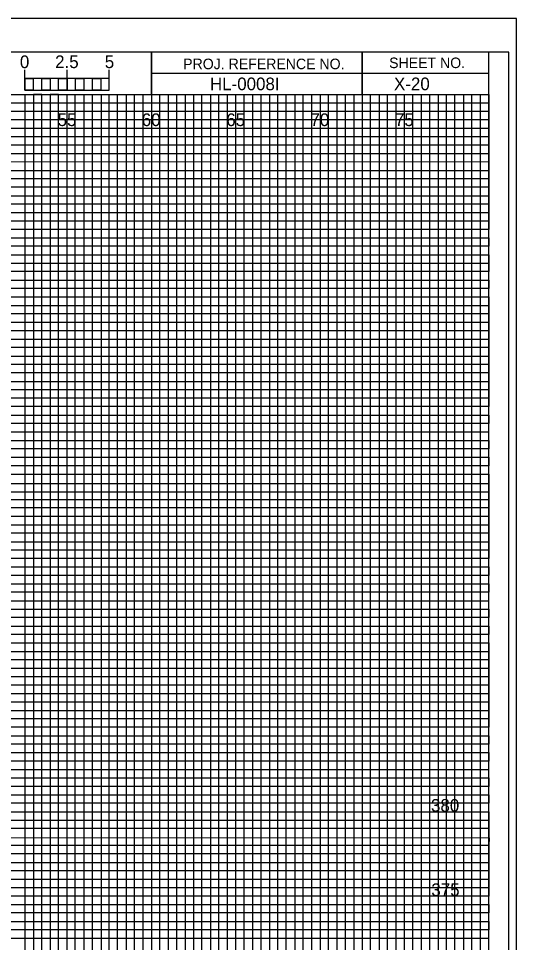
# Model space of a CAD drawing. Extents: x -7 to 162, y -2 to 327.
# Drawn here: x 132.1 to 161.7, y 272.2 to 327 of the extents above; entities that cross this region are included whole.
import ezdxf

# ---------------------------------------------------------------- set-up
doc = ezdxf.new("R2010")
doc.units = 0
for name, color, linetype in [('Exist Cross Section Cell', 7, 'Continuous'), ('Exist XS Center Line Elevation Label', 7, 'Continuous'), ('Prop CMT Conc Surface', 7, 'Continuous'), ('Prop CMT Concrete Structures', 7, 'Continuous'), ('Prop CMT Pvmt Course 1', 7, 'Continuous'), ('Prop CMT Pvmt Course 2', 7, 'Continuous'), ('Prop CMT Pvmt Course 3', 7, 'Continuous'), ('Prop CMT Shld Paved Course 1', 7, 'Continuous'), ('Prop CMT Shld Paved Course 2', 7, 'Continuous'), ('Prop CMT Shld Paved Course 3', 7, 'Continuous'), ('Prop CMT Slope Grass', 7, 'Continuous'), ('Prop CMT Subgrade Earthwork', 7, 'Continuous'), ('Scratch_Level_3', 7, 'Continuous')]:
    doc.layers.add(name, color=color, linetype=linetype)

msp = doc.modelspace()

# ---------------------------------------------------------------- linework, layer by layer
at = {"layer": 'Prop CMT Pvmt Course 2'}
for p, q in [((132.5, 322.745), (132.5, 323.95)), ((132.5, 323.45), (132.5, 323.95)), ((135, 322.745), (135, 323.95)), ((137.5, 322.745), (137.5, 323.95)), ((137.5, 323.45), (137.5, 323.95))]:
    msp.add_line(p, q, dxfattribs=at)
for points in [[(137.5, 323.45), (132.5, 323.45), (132.5, 322.745), (137.5, 322.745)], [(132.5, 323.45), (133, 323.45), (133, 322.745), (132.5, 322.745)], [(133.5, 323.45), (134, 323.45), (134, 322.745), (133.5, 322.745)], [(134.5, 323.45), (135, 323.45), (135, 322.745), (134.5, 322.745)], [(135.5, 323.45), (136, 323.45), (136, 322.745), (135.5, 322.745)], [(136.5, 323.45), (137, 323.45), (137, 322.745), (136.5, 322.745)]]:
    msp.add_lwpolyline(points, close=True, dxfattribs=at)
at = {"layer": 'Prop CMT Pvmt Course 3'}
msp.add_lwpolyline([(-6.7, 217.5), (161.65, 217.5), (161.65, 327), (-6.7, 327)], close=True, dxfattribs=at)
at = {"layer": 'Prop CMT Shld Paved Course 1'}
msp.add_line((0, 322), (160, 322), dxfattribs=at)
for points in [[(0, 321.5), (135, 321.5), (160, 321.5)], [(160, 321), (0, 321)], [(0, 320.5), (160, 320.5)], [(160, 319.5), (0, 319.5)], [(0, 319), (160, 319)], [(160, 318.5), (0, 318.49)], [(0, 318), (160, 318)], [(160, 317), (0, 317)], [(0, 316.5), (160, 316.5), (160, 316), (0, 316)], [(0, 315.5), (160, 315.5), (160, 314.5), (0, 314.5)], [(0, 314), (160, 314), (160, 313.5), (0, 313.5)], [(0, 313), (160, 313), (160, 312), (0, 312)], [(0, 311.5), (160, 311.5), (160, 311), (0, 311)], [(0, 310.5), (160, 310.5), (160, 309.5), (0, 309.5)], [(0, 309), (160, 309), (160, 308.5), (0, 308.5)], [(0, 308), (160, 308), (160, 306.975), (160, 306.5), (160, 306), (0, 306)], [(0, 307), (160, 307), (160, 306.5), (0, 306.5)], [(0, 305.5), (160, 305.5), (160, 304.5), (0, 304.515)], [(0, 304.515), (160, 304.5), (160, 304), (0, 304)], [(0, 303.5), (160, 303.5), (160, 303), (0, 303)], [(0, 302), (160, 302), (160, 301.5), (0, 301.5)], [(0, 301), (160, 301), (160, 300.5), (0, 300.5)], [(-0.035, 299.445), (160, 299.445), (160, 298.94), (-0.035, 298.94)], [(0, 298.5), (160, 298.5), (160, 298), (0, 298)], [(0, 297), (160, 297), (160, 296.5), (0, 296.5)], [(0, 296), (160, 296), (160, 295.5), (0, 295.5)], [(0, 294.5), (160, 294.5), (160, 294), (0, 294)], [(0, 293.5), (160, 293.5), (160, 293), (0, 293)], [(0, 292), (160, 292), (160, 291.5), (0, 291.5)], [(0, 291), (160, 291), (160, 290.5), (0, 290.5)], [(0, 289.5), (160, 289.5), (159.995, 288.99), (0, 289)], [(0, 288.5), (160, 288.5), (160, 288), (0, 288)], [(0, 287), (160, 287), (160, 286.5), (0, 286.5)], [(0, 286), (160, 286), (160, 285.5), (0, 285.5)], [(0, 284.5), (160, 284.5), (160, 284), (0, 284)], [(0, 283.5), (160, 283.5), (160, 283), (0, 283)], [(0, 282), (160, 282), (160, 281.5), (0, 281.5)], [(0, 281), (160, 281), (160, 280.5), (0, 280.5)], [(0, 279.5), (160, 279.5), (160, 279), (0, 279)], [(0, 278.495), (160.035, 278.455), (160, 278), (0, 278)], [(0, 277), (160, 277), (160, 276.5), (0, 276.5)], [(0, 276), (160, 276), (160, 275.5), (0, 275.5)], [(0, 274.5), (160, 274.5), (160, 274), (0, 274)], [(0, 273.5), (160, 273.5), (160, 273), (0, 273)]]:
    msp.add_lwpolyline(points, dxfattribs=at)
at = {"layer": 'Prop CMT Shld Paved Course 2'}
for p, q in [((152.5, 325), (152.5, 322.5)), ((152.5, 322.5), (152.5, 325)), ((140, 323.75), (140, 322.5)), ((160, 323.745), (140, 323.745)), ((140, 322.5), (160, 322.5))]:
    msp.add_line(p, q, dxfattribs=at)
for points in [[(160, 325), (0, 325), (0, 220), (160, 220)], [(140, 325), (130, 325), (130, 322.5), (140, 322.5)], [(160, 325), (140, 325), (140, 322.5), (160, 322.5)]]:
    msp.add_lwpolyline(points, close=True, dxfattribs=at)
at = {"layer": 'Prop CMT Shld Paved Course 3'}
for p, q in [((133.5, 322.5), (133.005, 322.5)), ((133.005, 322.5), (133.005, 220)), ((133.5, 220), (133.5, 322.5)), ((134.5, 322.5), (134, 322.5)), ((134, 322.5), (134, 220)), ((134.5, 220), (134.5, 322.5))]:
    msp.add_line(p, q, dxfattribs=at)
for points in [[(135, 220), (135.49, 220), (135.49, 322.5), (136, 322.5), (136, 220)], [(136, 220), (136.5, 220), (136.5, 322.5), (137.025, 322.5), (137.025, 220)], [(137.5, 220), (138, 220), (138, 322.5), (138.5, 322.5), (138.5, 220)], [(138.5, 220), (139, 220), (139, 322.5), (139.5, 322.5), (139.5, 220)], [(140, 220), (140.5, 220), (140.5, 322.5)], [(141, 322.5), (141, 220)], [(141, 220), (141.5, 220), (141.5, 322.5)], [(142, 322.5), (142, 220)], [(142.5, 220), (143, 220), (143, 322.5)], [(143.5, 322.5), (143.5, 220)], [(143.5, 220), (144, 220), (144, 322.5)], [(144.5, 322.5), (144.5, 220)], [(145, 220), (145.5, 220), (145.5, 322.5)], [(146, 322.5), (146, 220)], [(146, 220), (146.5, 220), (146.5, 322.5)], [(147, 322.5), (147, 220)], [(147.5, 220), (148, 220), (148, 322.5)], [(148.5, 322.5), (148.5, 220)], [(148.5, 220), (149, 220), (149, 322.5)], [(149.5, 322.5), (149.5, 220)], [(150, 220), (150.5, 220), (150.5, 322.5)], [(151, 322.5), (151, 220)], [(151, 220), (151.5, 220), (151.5, 322.5)], [(152, 322.5), (152, 220)], [(152.5, 220), (153, 220), (153, 322.5)], [(153.5, 322.5), (153.5, 220)], [(153.5, 220), (154, 220), (154, 322.5)], [(154.5, 322.5), (154.5, 220)], [(155, 220), (155.5, 220), (155.5, 322.5)], [(156, 322.5), (156, 220)], [(156, 220), (156.5, 220), (156.5, 322.5)], [(157, 322.5), (157, 220)], [(157.5, 220), (158, 220), (158, 322.5)], [(158.5, 322.5), (158.5, 220)], [(158.5, 220), (159, 220), (159, 322.5)], [(159.5, 322.5), (159.5, 220)]]:
    msp.add_lwpolyline(points, dxfattribs=at)
at = {"layer": 'Prop CMT Slope Grass'}
for points in [[(127.5, 325), (129.965, 325), (130, 325), (130, 322.5), (132.495, 322.5), (132.495, 220), (137.5, 220), (137.5, 322.5), (140, 322.5)], [(0, 322.5), (137.5, 322.5)], [(0, 312.5), (160, 312.5), (160, 322.5)], [(142.5, 322.5), (142.5, 220), (147.5, 220), (147.5, 322.5)], [(152.5, 322.5), (152.5, 220), (157.5, 220), (157.5, 322.5)], [(160, 317.5), (0, 317.5)], [(0, 302.5), (160, 302.5), (160, 307.5), (0, 307.5)], [(0, 292.5), (160, 292.5), (160, 297.5), (0, 297.5)], [(0, 282.5), (160, 282.5), (160, 287.5), (0, 287.5)], [(0, 272.5), (160, 272.5), (160, 277.5), (0, 277.5)]]:
    msp.add_lwpolyline(points, dxfattribs=at)
at = {"layer": 'Prop CMT Subgrade Earthwork'}
msp.add_lwpolyline([(-5.4, 219.5), (161.2, 219.5), (161.2, 325), (-5.4, 325)], close=True, dxfattribs=at)
at = {"layer": 'Scratch_Level_3'}
for p, q in [((135, 220), (135, 322.5)), ((140, 322.5), (140, 220)), ((145, 220), (145, 322.5)), ((150, 322.5), (150, 220)), ((155, 220), (155, 322.5))]:
    msp.add_line(p, q, dxfattribs=at)
for points in [[(160, 322.5), (160, 315), (0, 315)], [(0, 320), (160, 320)], [(0, 310), (160, 310), (160, 305), (0, 305)], [(0, 300), (160, 300), (160, 295), (0, 295)], [(0, 290), (160, 290), (160, 285), (0, 285)], [(0, 280), (160, 280), (160, 275), (0, 275)]]:
    msp.add_lwpolyline(points, dxfattribs=at)

# ---------------------------------------------------------------- texts
at = {"layer": 'Exist Cross Section Cell'}
for s, p in [('60', (139.429, 320.625)), ('65', (144.441, 320.625)), ('70', (149.429, 320.625)), ('55', (134.441, 320.625)), ('75', (154.441, 320.625))]:
    msp.add_text(s, height=0.75, dxfattribs=at).set_placement(p)
at = {"layer": 'Exist XS Center Line Elevation Label'}
msp.add_text('X-20', height=0.75, dxfattribs=at).set_placement((154.386, 322.75))
at = {"layer": 'Prop CMT Conc Surface'}
for s, p in [('2.5', (134.292, 324.06)), ('5', (137.237, 324.06))]:
    msp.add_text(s, height=0.75, dxfattribs=at).set_placement(p)
at = {"layer": 'Prop CMT Concrete Structures'}
msp.add_text('HL-0008I', height=0.75, dxfattribs=at).set_placement((143.474, 322.75))
at = {"layer": 'Prop CMT Pvmt Course 1'}
for s, p in [('380', (156.579, 280)), ('375', (156.599, 275))]:
    msp.add_text(s, height=0.75, dxfattribs=at).set_placement(p)
at = {"layer": 'Prop CMT Pvmt Course 2'}
msp.add_text('0', height=0.75, rotation=360, dxfattribs=at).set_placement((132.205, 324.06))
at = {"layer": 'Prop CMT Shld Paved Course 2'}
for s, height, p in [('SHEET NO.', 0.625, (154.095, 324.06)), ('PROJ. REFERENCE NO.', 0.62499, (141.885, 323.995))]:
    msp.add_text(s, height=height, rotation=360, dxfattribs=at).set_placement(p)

doc.saveas('drawing.dxf')
